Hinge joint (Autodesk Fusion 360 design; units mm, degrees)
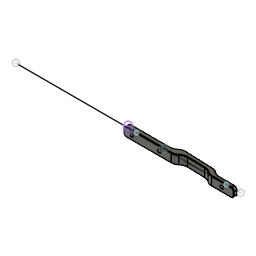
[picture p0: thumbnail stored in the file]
part number: 2025-11-16-08-20-10-952
parameter "d18" = 3.5
sketch "Sketch1" plane through (0, 0, 0) normal (0, 0, 1) x axis (1, 0, 0)
  line L1 (60, 0) -> (0, 0)
  line L2 (60, 5) -> (60, 0)
  line L3 (50, 5) -> (50, 10)
  line L4 (0, 5) -> (50, 5)
  line L5 (0, 0) -> (0, 5)
  line L6 (88.248, 4.1122) -> (60, 5)
  line L7 (88.248, 0.1122) -> (88.248, 4.1122)
  line L8 (119.9999, 0.1122) -> (88.248, 0.1122)
  line L9 (96.1637, 8.1089) -> (50, 10)
  line L10 (96.1637, 8.1089) -> (95.9999, 4.1122)
  line L11 (119.9999, 0.1122) -> (119.9999, 4.1122)
  line L12 (119.9999, 4.1122) -> (95.9999, 4.1122)
  point P1 (0, 0)
  point P2 (0, 0)
  point P8 (0, 0)
  point P3 (60, 0)
  point P4 (60, 5)
  point P5 (50, 10)
  point P6 (50, 5)
  point P11 (119.9999, 0.1122)
  point P12 (119.9999, 4.1122)
  point P13 (95.9999, 4.1122)
  point P7 (0, 5)
  point P9 (88.248, 4.1122)
  point P14 (96.1637, 8.1089)
  coincident P1 P2
  coincident P1 P8
  horizontal L8
  horizontal L1
  perpendicular L7 L8
  perpendicular L11 L12
  perpendicular L9 L10
  parallel L8 L12
  dimension "d1" distance P2 P3 = 60
  dimension "d2" distance P3 P4 = 5
  dimension "d6" distance P5 P6 = 5
  dimension "d53" distance P4 P6 = 10
  dimension "d55" distance P1 P11 = 120
  dimension "d60" distance P12 P13 = 24
  dimension "d61" distance P11 P12 = 4
  dimension "d72" distance P7 P8 = 5
  dimension "d75" distance P9 L8 = 4
  dimension "d76" distance P13 P14 = 4
extrude "Extrude1" new body sketch "Sketch1" along normal blind 10
fillet "Fillet5" radius 3 3
fillet "Fillet1" radius 9 9 9 9
sketch "Sketch2" plane through (0, 5, 0) normal (0, 1, 0) x axis (-1, 0, 0)
  line L1 (122.4456, 5) -> (-122.4456, 5)
  line L2 (0, 7) -> (0, 3)
  circle C1 centre (-9, 5) radius 1.75
  circle C2 centre (-39, 5) radius 1.75
  circle C3 centre (-107, 5) radius 1.75
  point P3 (-39, 5)
  point P2 (-9, 5)
  point P4 (-107, 5)
  horizontal L1
  midpoint L1 L2
  coincident P3 L1
  dimension "d17" diameter C1 = 3.5
  dimension "d19" diameter C2 = 3.5 (= "d17")
  dimension "d21" diameter C3 = 3.5 (= "d19")
  dimension "d73" distance P2 P3 = 30
  dimension "d74" distance P3 P4 = 68
extrude "Extrude2" cut sketch "Sketch2" profile of C1 C2 C3 L1 distance -16
fillet "Fillet8" radius 10
fillet "Fillet9" radius 0.5 0.5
